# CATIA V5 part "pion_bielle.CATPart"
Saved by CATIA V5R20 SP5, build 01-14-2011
Part number: pion_bielle
Bounding box of the stored display mesh (mm): x -102.654 to -92.654, y -34.22 to -21, z 157.141 to 167.141
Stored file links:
  F:\iao\catia\projet iao\pion_bielle.CATPart
  F:\iao\catia\projet iao\fhartmann.CATProduct
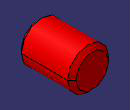
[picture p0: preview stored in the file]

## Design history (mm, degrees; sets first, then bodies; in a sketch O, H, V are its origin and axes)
External parameters (linked from other documents)
  External.bielle1_epaisseur = 6.61 mm
  External.bielle_diametre_int = 10 mm
Set1
  Plane1: linked copy from another document
  Point1: linked copy from another document
Body1 (main body)
  Sketch1 on Plane1, origin (0, -34.22, 0), H (-1, 0, 0), V (0, 0, 1)
    circle A1 centre (97.6544, 162.1409) radius 5
    point P1 (97.6544, 162.1409)
    reference projected point E1 (97.6544, 162.1409) from Point1
    radius A1 = 5 {= External.bielle_diametre_int /2}
    coincidence: P1 E1
  Pad1: profile Sketch1, direction (0, 1, 0), length 13.22 {= 2*External.bielle1_epaisseur}
  Chamfer1: length 1, angle 45, on edge [start face of Pad1 | face of Pad1 from Sketch1.A1]; edge [face of Pad1 from Sketch1.A1 | end face of Pad1]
